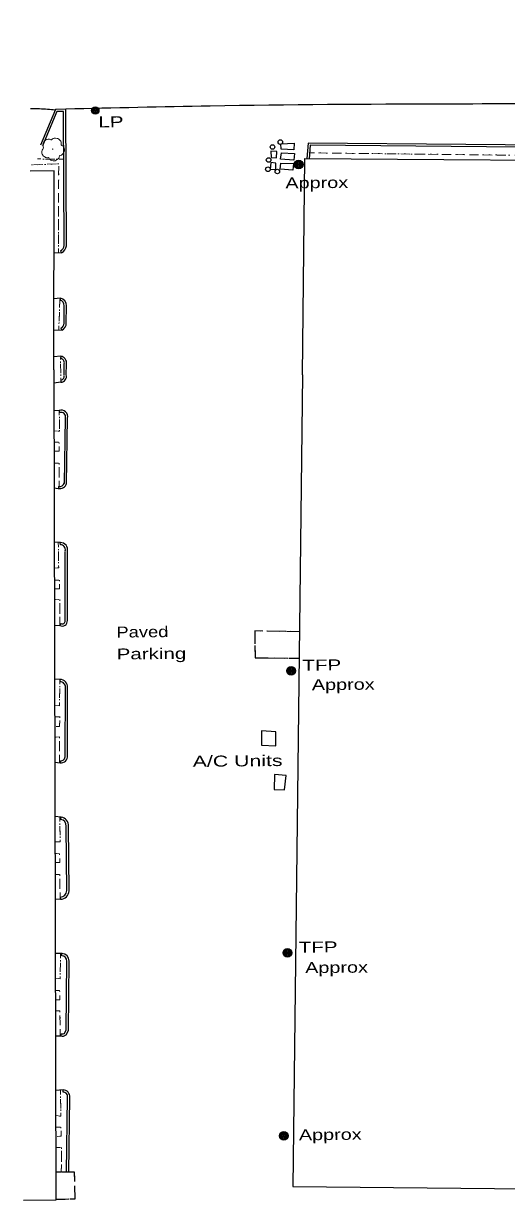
# Model space of a CAD drawing. Extents: x 2362213 to 2366494, y 6968794 to 6978110.
# Drawn here: x 2363861 to 2364072, y 6975301 to 6975816 of the extents above; entities that cross this region are included whole.
import ezdxf

# ---------------------------------------------------------------- set-up
doc = ezdxf.new("R2010")
doc.units = 0
doc.header["$LTSCALE"] = 1.9
for name, pattern in [('DASH_DOUBLE_DOT', [9.2, 5, -1.2, 0.3, -1.2, 0.3, -1.2]), ('DOTTED', [1.5, 0.3, -1.2]), ('MEDIUM_DASHED', [4.5, 3, -1.5])]:
    doc.linetypes.add(name, pattern=pattern)
for name, color, linetype, lineweight in [('11', 7, 'Continuous', 25), ('12', 7, 'Continuous', 25), ('13', 7, 'Continuous', 13), ('2', 7, 'Continuous', 25), ('20', 7, 'Continuous', 25), ('23', 7, 'Continuous', 25), ('25', 7, 'Continuous', 25), ('29', 7, 'Continuous', 13)]:
    doc.layers.add(name, color=color, linetype=linetype, lineweight=lineweight)

msp = doc.modelspace()

# ---------------------------------------------------------------- linework, layer by layer
at = {"layer": '11'}
for points in [[(2363982.848, 6975662.41), (2363983.886, 6975757.095), (2364146.266, 6975755.911), (2364145.539, 6975730.323), (2364150.759, 6975730.352), (2364150.226, 6975680.264), (2364145.077, 6975680.125), (2364144.59, 6975659.93)], [(2363874.012, 6975664.624), (2363874.132, 6975751.699), (2363863.673, 6975751.62)], [(2363874.012, 6975664.624), (2363874.994, 6975301.055), (2363860.805, 6975300.98)], [(2363982.848, 6975662.41), (2363978.601, 6975307.142), (2364140.395, 6975305.463), (2364140.804, 6975330.719), (2364145.825, 6975330.666), (2364146.589, 6975380.696), (2364141.338, 6975380.606), (2364141.712, 6975430.622), (2364147.015, 6975430.402), (2364147.958, 6975480.533), (2364142.276, 6975480.599), (2364142.448, 6975505.642), (2364148.032, 6975505.265), (2364148.793, 6975555.576), (2364143.044, 6975555.461), (2364143.564, 6975580.656), (2364148.896, 6975580.507), (2364149.503, 6975630.145), (2364144.578, 6975629.678), (2364144.59, 6975659.93)]]:
    msp.add_lwpolyline(points, dxfattribs=at)
at = {"layer": '12'}
for p, q in [((2363975.508, 6975550.085), (2363967.506, 6975550.228)), ((2363981.508, 6975549.972), (2363977.507, 6975550.044)), ((2363966.818, 6975538.501), (2363974.819, 6975538.447)), ((2363976.818, 6975538.436), (2363981.368, 6975538.41)), ((2363877.097, 6975313.367), (2363874.956, 6975313.386)), ((2363874.989, 6975301.495), (2363878.99, 6975301.603))]:
    msp.add_line(p, q, dxfattribs=at)
at = {"layer": '12', "linetype": 'MEDIUM_DASHED'}
for points in [[(2363981.508, 6975549.972), (2363961.944, 6975550.325), (2363962.176, 6975538.527), (2363981.368, 6975538.41)], [(2363874.989, 6975301.495), (2363883.399, 6975301.725), (2363883.108, 6975313.304), (2363874.956, 6975313.386)]]:
    msp.add_lwpolyline(points, dxfattribs=at)
at = {"layer": '12'}
for points in [[(2363965.505, 6975550.259), (2363961.944, 6975550.325), (2363962.036, 6975545.886)], [(2363962.075, 6975543.886), (2363962.176, 6975538.527), (2363964.817, 6975538.512)], [(2363883.206, 6975309.315), (2363883.108, 6975313.304), (2363879.098, 6975313.346)], [(2363880.989, 6975301.662), (2363883.399, 6975301.725), (2363883.255, 6975307.314)]]:
    msp.add_lwpolyline(points, dxfattribs=at)
at = {"layer": '13', "linetype": 'DOTTED'}
for p, q in [((2363878.435, 6975756.831), (2363866.882, 6975756.941)), ((2363876.197, 6975681.915), (2363876.742, 6975695.101)), ((2363877.184, 6975659.183), (2363876.934, 6975669.611))]:
    msp.add_line(p, q, dxfattribs=at)
at = {"layer": '13'}
for p, q in [((2363868.432, 6975756.925), (2363866.882, 6975756.941)), ((2363874.433, 6975756.872), (2363870.433, 6975756.904)), ((2363878.435, 6975756.831), (2363876.433, 6975756.851)), ((2363987.873, 6975759.583), (2363985.952, 6975759.604)), ((2363993.874, 6975759.51), (2363989.874, 6975759.562)), ((2363999.874, 6975759.437), (2363995.875, 6975759.489)), ((2364005.875, 6975759.364), (2364001.875, 6975759.416)), ((2364011.877, 6975759.301), (2364007.876, 6975759.343)), ((2364017.878, 6975759.228), (2364013.878, 6975759.28)), ((2364023.878, 6975759.156), (2364019.879, 6975759.208)), ((2364029.879, 6975759.083), (2364025.879, 6975759.135)), ((2364035.881, 6975759.02), (2364031.879, 6975759.062)), ((2364041.882, 6975758.947), (2364037.881, 6975758.999)), ((2364047.882, 6975758.874), (2364043.882, 6975758.926)), ((2364053.883, 6975758.801), (2364049.882, 6975758.853)), ((2364059.885, 6975758.738), (2364055.884, 6975758.78)), ((2364065.886, 6975758.666), (2364061.885, 6975758.717)), ((2364071.886, 6975758.593), (2364067.885, 6975758.645)), ((2363869.175, 6975754.512), (2363865.177, 6975754.354)), ((2363875.173, 6975754.759), (2363871.175, 6975754.591)), ((2363876.171, 6975749.808), (2363876.182, 6975753.809)), ((2363876.158, 6975743.807), (2363876.17, 6975747.808)), ((2363876.155, 6975737.808), (2363876.157, 6975741.807)), ((2363876.142, 6975731.808), (2363876.154, 6975735.808)), ((2363876.129, 6975725.806), (2363876.141, 6975729.807)), ((2363876.126, 6975719.806), (2363876.128, 6975723.806)), ((2363876.124, 6975715.807), (2363876.125, 6975717.806)), ((2363876.602, 6975691.91), (2363876.742, 6975695.101)), ((2363876.359, 6975685.918), (2363876.521, 6975689.909)), ((2363876.197, 6975681.915), (2363876.278, 6975683.916)), ((2363876.948, 6975669.182), (2363876.934, 6975669.611)), ((2363877.085, 6975663.183), (2363876.987, 6975667.183)), ((2363877.184, 6975659.183), (2363877.134, 6975661.183)), ((2363876.421, 6975646.825), (2363876.46, 6975644.827)), ((2363876.499, 6975642.827), (2363876.567, 6975638.826)), ((2363875.627, 6975637.807), (2363874.087, 6975637.843)), ((2363874.093, 6975633.003), (2363876.094, 6975632.902)), ((2363874.121, 6975623.702), (2363876.121, 6975623.741)), ((2363876.447, 6975622.075), (2363876.445, 6975618.075)), ((2363876.444, 6975616.074), (2363876.438, 6975613.564)), ((2363876.002, 6975589.029), (2363876.031, 6975587.029)), ((2363876.07, 6975585.029), (2363876.138, 6975581.03)), ((2363874.258, 6975572.601), (2363876.258, 6975572.6)), ((2363874.278, 6975564.151), (2363876.279, 6975564.09)), ((2363876.635, 6975562.434), (2363876.623, 6975558.433)), ((2363876.622, 6975556.433), (2363876.618, 6975552.684)), ((2363876.671, 6975525.052), (2363876.579, 6975521.051)), ((2363876.773, 6975529.053), (2363876.722, 6975527.053)), ((2363874.418, 6975512.73), (2363876.418, 6975512.779)), ((2363874.443, 6975503.79), (2363876.432, 6975503.959)), ((2363876.559, 6975502.1), (2363876.547, 6975498.1)), ((2363876.546, 6975496.1), (2363876.54, 6975492.59)), ((2363876.696, 6975468.83), (2363876.715, 6975466.83)), ((2363876.734, 6975464.83), (2363876.762, 6975460.829)), ((2363874.606, 6975443.679), (2363876.606, 6975443.668)), ((2363876.694, 6975441.739), (2363876.742, 6975437.738)), ((2363876.761, 6975435.739), (2363876.799, 6975432.859)), ((2363877.036, 6975409.03), (2363876.995, 6975407.03)), ((2363876.954, 6975405.029), (2363876.862, 6975401.028)), ((2363876.753, 6975381.977), (2363876.821, 6975377.977)), ((2363876.85, 6975375.977), (2363876.899, 6975373.016)), ((2363877.014, 6975349.297), (2363877.023, 6975347.297)), ((2363877.042, 6975345.297), (2363877.071, 6975341.298)), ((2363874.909, 6975333.087), (2363876.908, 6975333.136)), ((2363874.934, 6975324.126), (2363876.934, 6975324.125)), ((2363877.458, 6975322.67), (2363877.406, 6975318.67)), ((2363877.375, 6975316.669), (2363877.327, 6975313.359))]:
    msp.add_line(p, q, dxfattribs=at)
at = {"layer": '13', "linetype": 'DOTTED'}
for points in [[(2364149.849, 6975730.344), (2364150.508, 6975757.741), (2363985.952, 6975759.604)], [(2363876.124, 6975715.807), (2363876.183, 6975754.799), (2363863.687, 6975754.29)], [(2363876.421, 6975646.825), (2363876.587, 6975637.787), (2363874.087, 6975637.843)], [(2363874.093, 6975633.003), (2363876.314, 6975632.894), (2363876.431, 6975628.965), (2363874.111, 6975629.023)], [(2363874.121, 6975623.702), (2363876.451, 6975623.745), (2363876.438, 6975613.564)], [(2363876.002, 6975589.029), (2363876.187, 6975577.91), (2363874.249, 6975577.752)], [(2363874.258, 6975572.601), (2363876.488, 6975572.603), (2363876.494, 6975568.773), (2363874.274, 6975568.771)], [(2363874.278, 6975564.151), (2363876.639, 6975564.074), (2363876.618, 6975552.684)], [(2363876.773, 6975529.053), (2363876.502, 6975517.55), (2363874.41, 6975517.73)], [(2363874.418, 6975512.73), (2363876.688, 6975512.782), (2363876.498, 6975508.5), (2363874.438, 6975508.56)], [(2363874.443, 6975503.79), (2363876.562, 6975503.97), (2363876.54, 6975492.59)], [(2363876.696, 6975468.83), (2363876.789, 6975458.05), (2363874.569, 6975457.999)], [(2363874.588, 6975452.869), (2363876.539, 6975452.788), (2363876.716, 6975448.929), (2363874.596, 6975448.899)], [(2363874.606, 6975443.679), (2363876.676, 6975443.669), (2363876.799, 6975432.859)], [(2363877.036, 6975409.03), (2363876.79, 6975398.058), (2363874.729, 6975398.148)], [(2363874.749, 6975392.937), (2363876.599, 6975392.865), (2363876.748, 6975388.837), (2363874.757, 6975388.878)], [(2363874.774, 6975383.968), (2363876.724, 6975384.026), (2363876.899, 6975373.016)], [(2363877.014, 6975349.297), (2363877.093, 6975337.868), (2363874.891, 6975338.137)], [(2363874.909, 6975333.087), (2363877.168, 6975333.138), (2363877.287, 6975329.098), (2363874.918, 6975328.996)], [(2363874.934, 6975324.126), (2363877.474, 6975324.13), (2363877.327, 6975313.359)]]:
    msp.add_lwpolyline(points, dxfattribs=at)
at = {"layer": '13'}
for points in [[(2363876.371, 6975631.114), (2363876.431, 6975628.965), (2363874.581, 6975629.007)], [(2363876.167, 6975579.03), (2363876.187, 6975577.91), (2363874.249, 6975577.752)], [(2363876.495, 6975570.833), (2363876.494, 6975568.773), (2363874.554, 6975568.774)], [(2363876.538, 6975519.051), (2363876.502, 6975517.55), (2363874.41, 6975517.73)], [(2363876.614, 6975511.051), (2363876.498, 6975508.5), (2363875.048, 6975508.546)], [(2363876.781, 6975458.83), (2363876.789, 6975458.05), (2363874.569, 6975457.999)], [(2363874.588, 6975452.869), (2363876.539, 6975452.788), (2363876.539, 6975452.738)], [(2363876.628, 6975450.738), (2363876.716, 6975448.929), (2363874.596, 6975448.899)], [(2363876.811, 6975399.028), (2363876.79, 6975398.058), (2363874.729, 6975398.148)], [(2363874.749, 6975392.937), (2363876.599, 6975392.865), (2363876.601, 6975392.715)], [(2363876.68, 6975390.715), (2363876.748, 6975388.837), (2363874.757, 6975388.878)], [(2363874.774, 6975383.968), (2363876.724, 6975384.026), (2363876.724, 6975383.976)], [(2363877.08, 6975339.298), (2363877.093, 6975337.868), (2363874.891, 6975338.137)], [(2363877.215, 6975331.399), (2363877.287, 6975329.098), (2363875.587, 6975329.022)]]:
    msp.add_lwpolyline(points, dxfattribs=at)
at = {"layer": '2'}
for p, q in [((2363877.404, 6975715.848), (2363874.085, 6975715.747)), ((2363876.986, 6975716.714), (2363877.404, 6975715.848)), ((2363876.983, 6975696.033), (2363874.056, 6975695.695)), ((2363876.983, 6975696.033), (2363876.742, 6975695.101)), ((2363878.548, 6975685.108), (2363878.596, 6975692.618)), ((2363879.508, 6975685.097), (2363879.556, 6975692.608)), ((2363877.517, 6975681.957), (2363874.038, 6975681.844)), ((2363877.128, 6975682.834), (2363877.517, 6975681.957)), ((2363877.055, 6975670.562), (2363874.018, 6975670.254)), ((2363877.055, 6975670.562), (2363876.934, 6975669.611)), ((2363878.564, 6975662.377), (2363878.638, 6975667.178)), ((2363879.524, 6975662.367), (2363879.599, 6975667.168)), ((2363877.184, 6975659.183), (2363874.027, 6975658.803)), ((2363877.104, 6975660.142), (2363877.184, 6975659.183)), ((2363876.421, 6975646.825), (2363874.063, 6975646.673)), ((2363876.71, 6975645.909), (2363876.431, 6975646.825)), ((2363878.676, 6975614.925), (2363879.104, 6975643.462)), ((2363879.636, 6975614.915), (2363880.064, 6975643.451)), ((2363874.154, 6975612.892), (2363875.957, 6975612.659)), ((2363876.138, 6975613.601), (2363876.067, 6975612.64)), ((2363876.922, 6975588.978), (2363874.22, 6975589.142)), ((2363876.911, 6975588.017), (2363876.882, 6975588.977)), ((2363879.058, 6975554.836), (2363879.03, 6975585.127)), ((2363880.018, 6975554.835), (2363879.99, 6975585.127)), ((2363874.316, 6975552.892), (2363876.648, 6975552.684)), ((2363877.08, 6975553.537), (2363876.648, 6975552.684)), ((2363876.803, 6975529.054), (2363874.381, 6975529.171)), ((2363876.772, 6975528.093), (2363876.773, 6975529.053)), ((2363879.011, 6975495.743), (2363879.147, 6975525.586)), ((2363879.971, 6975495.742), (2363880.107, 6975525.585)), ((2363874.478, 6975492.8), (2363876.78, 6975492.562)), ((2363876.911, 6975493.513), (2363876.78, 6975492.562)), ((2363877.257, 6975468.765), (2363874.544, 6975469.059)), ((2363877.106, 6975467.814), (2363877.227, 6975468.765)), ((2363879.774, 6975436.568), (2363879.486, 6975464.766)), ((2363880.734, 6975436.577), (2363880.446, 6975464.775)), ((2363874.637, 6975433.009), (2363876.909, 6975432.85)), ((2363876.9, 6975433.81), (2363876.909, 6975432.85)), ((2363877.667, 6975409.026), (2363874.705, 6975409.068)), ((2363877.605, 6975408.066), (2363877.627, 6975409.026)), ((2363874.797, 6975373.116), (2363877.169, 6975373.009)), ((2363877.32, 6975373.941), (2363877.169, 6975372.989)), ((2363878.125, 6975349.367), (2363874.866, 6975349.146)), ((2363878.084, 6975348.407), (2363878.095, 6975349.367)), ((2363879.618, 6975313.341), (2363880.076, 6975346.106)), ((2363880.578, 6975313.33), (2363881.036, 6975346.095))]:
    msp.add_line(p, q, dxfattribs=at)
for points in [[(2363879.605, 6975718.959), (2363879.276, 6975778.74), (2363874.796, 6975778.617), (2363868.154, 6975763.022)], [(2363878.645, 6975718.95), (2363878.326, 6975777.75), (2363875.435, 6975777.673), (2363869.038, 6975762.65)], [(2364111.015, 6975781.006), (2364123.26, 6975762.682), (2363985.381, 6975763.908), (2363984.756, 6975757.093)], [(2364112.916, 6975779.884), (2364125.069, 6975761.709), (2363986.261, 6975762.938), (2363985.717, 6975757.002)], [(2363878.611, 6975373.893), (2363879.495, 6975375.562), (2363879.818, 6975405.777)], [(2363879.456, 6975373.441), (2363880.458, 6975375.321), (2363880.778, 6975405.766)]]:
    msp.add_lwpolyline(points, dxfattribs=at)
for centre, radius, start, end in [((2363875.698, 6975719.387), 2.969, 295.73941, 353.75197), ((2363875.698, 6975719.387), 3.929, 295.73941, 353.75197), ((2363876.138, 6975692.719), 2.459, 358.13223, 75.70464), ((2363876.138, 6975692.719), 3.419, 358.13223, 75.70464), ((2363876.147, 6975685.027), 2.402, 294.05081, 1.18268), ((2363876.147, 6975685.027), 3.362, 294.05081, 1.18268), ((2363876.69, 6975667.639), 1.986, 350.77037, 82.88516), ((2363876.69, 6975667.639), 2.946, 350.77037, 82.88516), ((2363876.975, 6975661.787), 1.652, 274.58211, 12.79368), ((2363876.975, 6975661.787), 2.612, 274.58211, 12.79368), ((2363877.284, 6975644.102), 2.855, 346.80451, 107.57173), ((2363877.284, 6975644.102), 1.895, 346.80451, 107.57173), ((2363876.558, 6975615.804), 3.201, 259.17514, 343.88897), ((2363876.558, 6975615.804), 2.241, 259.17514, 343.88897), ((2363876.969, 6975585.869), 3.11, 346.18869, 91.60522), ((2363876.969, 6975585.869), 2.15, 346.18869, 91.60522), ((2363877.694, 6975554.76), 2.325, 243.26846, 1.86551), ((2363877.694, 6975554.76), 1.365, 243.26846, 1.86551), ((2363876.786, 6975525.729), 3.323, 357.51696, 90.23261), ((2363876.786, 6975525.729), 2.363, 357.51696, 90.23261), ((2363877.17, 6975495.359), 2.825, 262.07248, 7.78647), ((2363877.17, 6975495.359), 1.865, 262.07248, 7.78647), ((2363876.769, 6975465.103), 3.691, 354.90281, 82.87174), ((2363876.769, 6975465.103), 2.731, 354.90281, 82.87174), ((2363876.874, 6975436.71), 2.9, 270.51792, 358.01623), ((2363876.874, 6975436.71), 3.86, 270.51792, 358.01623), ((2363877.55, 6975405.8), 2.267, 359.397, 88.65726), ((2363877.55, 6975405.8), 3.227, 359.397, 88.65726), ((2363877.786, 6975375.89), 2.962, 256.58824, 304.27689), ((2363877.786, 6975375.89), 2.002, 256.58824, 304.27689), ((2363878.065, 6975346.383), 2.025, 354.47538, 89.4361), ((2363878.065, 6975346.383), 2.985, 354.47538, 89.4361)]:
    msp.add_arc(centre, radius, start, end, dxfattribs=at)
for points in [[(2363874.679, 6975778.346), (2363867.824, 6975778.82), (2363863.854, 6975778.823)], [(2364111.015, 6975781.006), (2364045.031, 6975780.968), (2363942.485, 6975780.081), (2363879.276, 6975778.74)]]:
    msp.add_spline(points, degree=3, dxfattribs=at)
at = {"layer": '20'}
for centre, radius in [((2363892.201, 6975778.172), 1.6), ((2363892.201, 6975778.172), 1.3), ((2363892.201, 6975778.172), 1), ((2363892.201, 6975778.172), 0.539), ((2363892.201, 6975778.172), 0.192), ((2363981.191, 6975754.498), 1.9), ((2363981.191, 6975754.498), 1.442), ((2363981.191, 6975754.498), 0.973), ((2363981.191, 6975754.498), 0.539), ((2363981.191, 6975754.498), 0.192), ((2363977.852, 6975532.846), 1.9), ((2363977.852, 6975532.846), 1.442), ((2363977.852, 6975532.846), 0.973), ((2363977.852, 6975532.846), 0.539), ((2363977.852, 6975532.846), 0.192), ((2363976.257, 6975409.395), 1.9), ((2363976.257, 6975409.395), 1.442), ((2363976.257, 6975409.395), 0.973), ((2363976.257, 6975409.395), 0.539), ((2363976.257, 6975409.395), 0.192), ((2363974.67, 6975329.246), 1.9), ((2363974.67, 6975329.246), 1.442), ((2363974.67, 6975329.246), 0.973), ((2363974.67, 6975329.246), 0.539), ((2363974.67, 6975329.246), 0.192)]:
    msp.add_circle(centre, radius, dxfattribs=at)
at = {"layer": '23'}
for points in [[(2363973.454, 6975763.625), (2363979.191, 6975763.919), (2363979.109, 6975760.959), (2363973.468, 6975761.196)], [(2363971.647, 6975760.178), (2363969.036, 6975760.303), (2363969.162, 6975757.554), (2363971.494, 6975757.357)], [(2363973.642, 6975759.667), (2363979.385, 6975759.292), (2363979.032, 6975756.438), (2363973.309, 6975756.874)], [(2363971.225, 6975755.164), (2363968.963, 6975755.322), (2363968.712, 6975752.29), (2363971.211, 6975752.414)], [(2363973.345, 6975755.164), (2363978.916, 6975755.007), (2363978.664, 6975752.075), (2363973.131, 6975752.412)], [(2363971.185, 6975506.211), (2363964.941, 6975506.532), (2363964.97, 6975500.302), (2363971.174, 6975500.081)], [(2363975.669, 6975486.983), (2363970.574, 6975487.485), (2363970.467, 6975480.833), (2363975.038, 6975480.797)]]:
    msp.add_lwpolyline(points, close=True, dxfattribs=at)
for centre in [(2363969.717, 6975762.19), (2363973.157, 6975764.322), (2363968.032, 6975756.483), (2363967.73, 6975752.44), (2363971.86, 6975751.419)]:
    msp.add_circle(centre, 1, dxfattribs=at)
at = {"layer": '25', "linetype": 'DASH_DOUBLE_DOT'}
msp.add_spline([(2364310.491, 6975656.319), (2364309.315, 6975672.72), (2364298.364, 6975726.467), (2364286.692, 6975764.268), (2364256.739, 6975841.117), (2364237.482, 6975880.675), (2364207.194, 6975936.919), (2364187.287, 6975969.191), (2364152.962, 6976013.656), (2364115.828, 6976058.935), (2364082.642, 6976102.511), (2364057.611, 6976141.394), (2364041.755, 6976162.894), (2364026.344, 6976185.928), (2364018.13, 6976197.872), (2364016.1, 6976205.372), (2364015.847, 6976210.94), (2364013.084, 6976216.455), (2364009.051, 6976219.846), (2363997.967, 6976222.231), (2363988.629, 6976226.282), (2363979.044, 6976231.97), (2363962.438, 6976249.274), (2363954.619, 6976263.83), (2363947.844, 6976280.085), (2363938.606, 6976306.129), (2363935.221, 6976325.478), (2363933.103, 6976340.059), (2363930.105, 6976355.511)], degree=3, dxfattribs=at)
at = {"layer": '29'}
msp.add_circle((2363873.582, 6975761.224), 0.1, dxfattribs=at)
for points in [[(2363877.294, 6975763.109), (2363878.435, 6975762.051), (2363878.72, 6975760.463), (2363878.013, 6975759.137), (2363877.357, 6975758.59), (2363876.689, 6975758.374), (2363876.539, 6975758.363), (2363876.52, 6975758.252), (2363876.199, 6975757.349), (2363874.66, 6975756.185), (2363872.767, 6975756.467), (2363871.868, 6975757.408), (2363871.797, 6975757.537), (2363871.677, 6975757.516), (2363870.466, 6975757.635), (2363869.196, 6975758.633), (2363868.851, 6975760.269), (2363869.221, 6975761.293), (2363869.547, 6975761.736), (2363869.616, 6975761.787)], [(2363869.616, 6975761.797), (2363869.636, 6975761.807), (2363869.555, 6975761.876), (2363869.319, 6975762.503), (2363869.357, 6975763.783), (2363870.245, 6975765.082), (2363871.55, 6975765.564), (2363872.672, 6975765.375), (2363872.903, 6975765.247), (2363872.973, 6975765.248), (2363873.023, 6975765.288), (2363873.37, 6975765.582), (2363874.236, 6975766.03), (2363875.447, 6975765.961), (2363876.562, 6975765.372), (2363877.296, 6975763.949), (2363877.304, 6975763.089)]]:
    msp.add_spline(points, degree=3, dxfattribs=at)

# ---------------------------------------------------------------- texts
at = {"layer": '2'}
for s, width, p in [('Paved', 1.25, (2363901.47, 6975547.399)), ('Parking', 1.4, (2363901.562, 6975537.8))]:
    msp.add_text(s, height=4.8, rotation=0.546, dxfattribs=dict(at, width=width)).set_placement(p)
at = {"layer": '20'}
for s, width, p in [('  LP', 1.4, (2363888.582, 6975770.687)), ('Approx', 1.35, (2363975.4, 6975744.012)), ('  TFP', 1.4, (2363977.851, 6975532.846)), ('Approx', 1.35, (2363986.992, 6975524.363)), ('  TFP', 1.4, (2363976.258, 6975409.395)), ('Approx', 1.35, (2363984.052, 6975400.489)), ('Approx', 1.35, (2363981.308, 6975327.309))]:
    msp.add_text(s, height=4.8, rotation=0.546, dxfattribs=dict(at, width=width)).set_placement(p)
at = {"layer": '23', "width": 1.45}
msp.add_text('A/C Units', height=4.8, rotation=0.546, dxfattribs=at).set_placement((2363934.859, 6975490.815))

doc.saveas('drawing.dxf')
